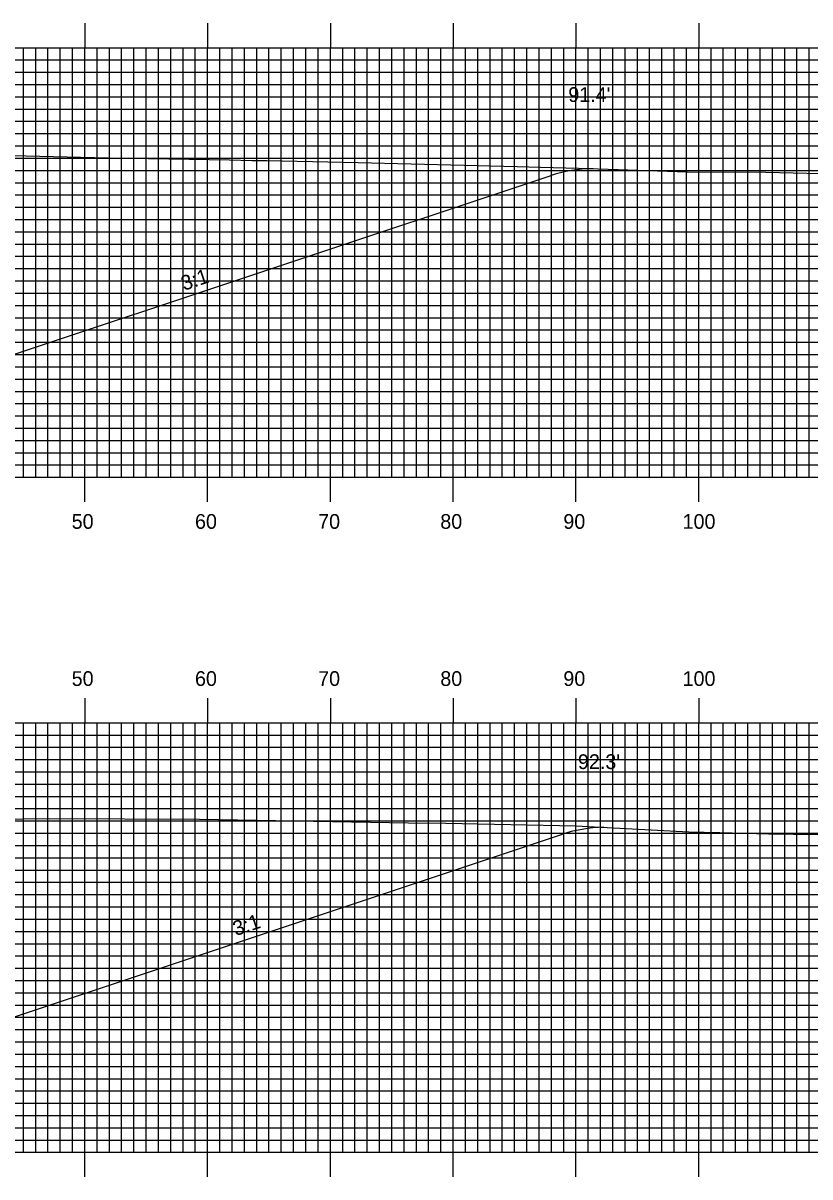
# Model space of a CAD drawing. Extents: x 1796420 to 1796763, y 442591 to 442811.
# Drawn here: x 1796630.9 to 1796695, y 442666.7 to 442760.7 of the extents above; entities that cross this region are included whole.
import ezdxf

# ---------------------------------------------------------------- set-up
doc = ezdxf.new("R2010")
doc.units = 0
for name, color, linetype in [('ANNOTATION', 7, 'Continuous'), ('D_Roadway_SlopeLines', 7, 'Continuous'), ('D_Text_Standard', 7, 'Continuous'), ('H_V ANNOTATION', 7, 'Continuous'), ('MAJOR', 7, 'Continuous'), ('MINOR', 7, 'Continuous'), ('S_Roadway_Centerline', 7, 'Continuous')]:
    doc.layers.add(name, color=color, linetype=linetype)

msp = doc.modelspace()

# ---------------------------------------------------------------- linework, layer by layer
at = {"layer": 'D_Roadway_SlopeLines'}
msp.add_line((1796620.079, 442730.323), (1796673.792, 442748.228), dxfattribs=at)
msp.add_lwpolyline([(1796621.053, 442678.665), (1796627.053, 442678.665), (1796674.718, 442694.554)], dxfattribs=at)
for centre, radius, start, end in [((1796677.352, 442737.548), 11.257, 90.17452, 108.43495), ((1796678.416, 442683.46), 11.694, 91.12543, 108.71551)]:
    msp.add_arc(centre, radius, start, end, dxfattribs=at)
at = {"layer": 'MAJOR'}
for p, q in [((1796635.905, 442760.669), (1796635.905, 442758.665)), ((1796645.905, 442760.669), (1796645.905, 442758.665)), ((1796655.905, 442760.669), (1796655.905, 442758.665)), ((1796665.905, 442760.669), (1796665.905, 442758.665)), ((1796675.905, 442760.669), (1796675.905, 442758.665)), ((1796685.905, 442760.669), (1796685.905, 442758.665)), ((1796445.905, 442758.665), (1796725.905, 442758.665)), ((1796445.905, 442758.665), (1796725.905, 442758.665)), ((1796635.905, 442723.665), (1796635.905, 442758.665)), ((1796645.905, 442723.665), (1796645.905, 442758.665)), ((1796655.905, 442723.665), (1796655.905, 442758.665)), ((1796665.905, 442723.665), (1796665.905, 442758.665)), ((1796675.905, 442723.665), (1796675.905, 442758.665)), ((1796685.905, 442723.665), (1796685.905, 442758.665)), ((1796445.905, 442753.665), (1796725.905, 442753.665)), ((1796445.905, 442748.665), (1796725.905, 442748.665)), ((1796445.905, 442743.665), (1796725.905, 442743.665)), ((1796445.905, 442738.665), (1796725.905, 442738.665)), ((1796445.905, 442733.665), (1796725.905, 442733.665)), ((1796445.905, 442728.665), (1796725.905, 442728.665)), ((1796445.905, 442723.665), (1796725.905, 442723.665)), ((1796445.905, 442723.665), (1796725.905, 442723.665)), ((1796635.905, 442721.661), (1796635.905, 442723.665)), ((1796645.905, 442721.661), (1796645.905, 442723.665)), ((1796655.905, 442721.661), (1796655.905, 442723.665)), ((1796665.905, 442721.661), (1796665.905, 442723.665)), ((1796675.905, 442721.661), (1796675.905, 442723.665)), ((1796685.905, 442721.661), (1796685.905, 442723.665)), ((1796635.905, 442705.669), (1796635.905, 442703.665)), ((1796645.905, 442705.669), (1796645.905, 442703.665)), ((1796655.905, 442705.669), (1796655.905, 442703.665)), ((1796665.905, 442705.669), (1796665.905, 442703.665)), ((1796675.905, 442705.669), (1796675.905, 442703.665)), ((1796685.905, 442705.669), (1796685.905, 442703.665)), ((1796445.905, 442703.665), (1796725.905, 442703.665)), ((1796445.905, 442703.665), (1796725.905, 442703.665)), ((1796635.905, 442668.665), (1796635.905, 442703.665)), ((1796645.905, 442668.665), (1796645.905, 442703.665)), ((1796655.905, 442668.665), (1796655.905, 442703.665)), ((1796665.905, 442668.665), (1796665.905, 442703.665)), ((1796675.905, 442668.665), (1796675.905, 442703.665)), ((1796685.905, 442668.665), (1796685.905, 442703.665)), ((1796445.905, 442698.665), (1796725.905, 442698.665)), ((1796445.905, 442693.665), (1796725.905, 442693.665)), ((1796445.905, 442688.665), (1796725.905, 442688.665)), ((1796445.905, 442683.665), (1796725.905, 442683.665)), ((1796445.905, 442678.665), (1796725.905, 442678.665)), ((1796445.905, 442673.665), (1796725.905, 442673.665)), ((1796445.905, 442668.665), (1796725.905, 442668.665)), ((1796445.905, 442668.665), (1796725.905, 442668.665)), ((1796635.905, 442666.661), (1796635.905, 442668.665)), ((1796645.905, 442666.661), (1796645.905, 442668.665)), ((1796655.905, 442666.661), (1796655.905, 442668.665)), ((1796665.905, 442666.661), (1796665.905, 442668.665)), ((1796675.905, 442666.661), (1796675.905, 442668.665)), ((1796685.905, 442666.661), (1796685.905, 442668.665))]:
    msp.add_line(p, q, dxfattribs=at)
at = {"layer": 'MINOR'}
for p, q in [((1796630.905, 442723.665), (1796630.905, 442758.665)), ((1796631.905, 442723.665), (1796631.905, 442758.665)), ((1796632.905, 442723.665), (1796632.905, 442758.665)), ((1796633.905, 442723.665), (1796633.905, 442758.665)), ((1796634.905, 442723.665), (1796634.905, 442758.665)), ((1796636.905, 442723.665), (1796636.905, 442758.665)), ((1796637.905, 442723.665), (1796637.905, 442758.665)), ((1796638.905, 442723.665), (1796638.905, 442758.665)), ((1796639.905, 442723.665), (1796639.905, 442758.665)), ((1796640.905, 442723.665), (1796640.905, 442758.665)), ((1796641.905, 442723.665), (1796641.905, 442758.665)), ((1796642.905, 442723.665), (1796642.905, 442758.665)), ((1796643.905, 442723.665), (1796643.905, 442758.665)), ((1796644.905, 442723.665), (1796644.905, 442758.665)), ((1796646.905, 442723.665), (1796646.905, 442758.665)), ((1796647.905, 442723.665), (1796647.905, 442758.665)), ((1796648.905, 442723.665), (1796648.905, 442758.665)), ((1796649.905, 442723.665), (1796649.905, 442758.665)), ((1796650.905, 442723.665), (1796650.905, 442758.665)), ((1796651.905, 442723.665), (1796651.905, 442758.665)), ((1796652.905, 442723.665), (1796652.905, 442758.665)), ((1796653.905, 442723.665), (1796653.905, 442758.665)), ((1796654.905, 442723.665), (1796654.905, 442758.665)), ((1796656.905, 442723.665), (1796656.905, 442758.665)), ((1796657.905, 442723.665), (1796657.905, 442758.665)), ((1796658.905, 442723.665), (1796658.905, 442758.665)), ((1796659.905, 442723.665), (1796659.905, 442758.665)), ((1796660.905, 442723.665), (1796660.905, 442758.665)), ((1796661.905, 442723.665), (1796661.905, 442758.665)), ((1796662.905, 442723.665), (1796662.905, 442758.665)), ((1796663.905, 442723.665), (1796663.905, 442758.665)), ((1796664.905, 442723.665), (1796664.905, 442758.665)), ((1796666.905, 442723.665), (1796666.905, 442758.665)), ((1796667.905, 442723.665), (1796667.905, 442758.665)), ((1796668.905, 442723.665), (1796668.905, 442758.665)), ((1796669.905, 442723.665), (1796669.905, 442758.665)), ((1796670.905, 442723.665), (1796670.905, 442758.665)), ((1796671.905, 442723.665), (1796671.905, 442758.665)), ((1796672.905, 442723.665), (1796672.905, 442758.665)), ((1796673.905, 442723.665), (1796673.905, 442758.665)), ((1796674.905, 442723.665), (1796674.905, 442758.665)), ((1796676.905, 442723.665), (1796676.905, 442758.665)), ((1796677.905, 442723.665), (1796677.905, 442758.665)), ((1796678.905, 442723.665), (1796678.905, 442758.665)), ((1796679.905, 442723.665), (1796679.905, 442758.665)), ((1796680.905, 442723.665), (1796680.905, 442758.665)), ((1796681.905, 442723.665), (1796681.905, 442758.665)), ((1796682.905, 442723.665), (1796682.905, 442758.665)), ((1796683.905, 442723.665), (1796683.905, 442758.665)), ((1796684.905, 442723.665), (1796684.905, 442758.665)), ((1796686.905, 442723.665), (1796686.905, 442758.665)), ((1796687.905, 442723.665), (1796687.905, 442758.665)), ((1796688.905, 442723.665), (1796688.905, 442758.665)), ((1796689.905, 442723.665), (1796689.905, 442758.665)), ((1796690.905, 442723.665), (1796690.905, 442758.665)), ((1796691.905, 442723.665), (1796691.905, 442758.665)), ((1796692.905, 442723.665), (1796692.905, 442758.665)), ((1796693.905, 442723.665), (1796693.905, 442758.665)), ((1796694.905, 442723.665), (1796694.905, 442758.665)), ((1796445.905, 442757.665), (1796725.905, 442757.665)), ((1796445.905, 442756.665), (1796725.905, 442756.665)), ((1796445.905, 442755.665), (1796725.905, 442755.665)), ((1796445.905, 442754.665), (1796725.905, 442754.665)), ((1796445.905, 442752.665), (1796725.905, 442752.665)), ((1796445.905, 442751.665), (1796725.905, 442751.665)), ((1796445.905, 442750.665), (1796725.905, 442750.665)), ((1796445.905, 442749.665), (1796725.905, 442749.665)), ((1796445.905, 442747.665), (1796725.905, 442747.665)), ((1796445.905, 442746.665), (1796725.905, 442746.665)), ((1796445.905, 442745.665), (1796725.905, 442745.665)), ((1796445.905, 442744.665), (1796725.905, 442744.665)), ((1796445.905, 442742.665), (1796725.905, 442742.665)), ((1796445.905, 442741.665), (1796725.905, 442741.665)), ((1796445.905, 442740.665), (1796725.905, 442740.665)), ((1796445.905, 442739.665), (1796725.905, 442739.665)), ((1796445.905, 442737.665), (1796725.905, 442737.665)), ((1796445.905, 442736.665), (1796725.905, 442736.665)), ((1796445.905, 442735.665), (1796725.905, 442735.665)), ((1796445.905, 442734.665), (1796725.905, 442734.665)), ((1796445.905, 442732.665), (1796725.905, 442732.665)), ((1796445.905, 442731.665), (1796725.905, 442731.665)), ((1796445.905, 442730.665), (1796725.905, 442730.665)), ((1796445.905, 442729.665), (1796725.905, 442729.665)), ((1796445.905, 442727.665), (1796725.905, 442727.665)), ((1796445.905, 442726.665), (1796725.905, 442726.665)), ((1796445.905, 442725.665), (1796725.905, 442725.665)), ((1796445.905, 442724.665), (1796725.905, 442724.665)), ((1796630.905, 442668.665), (1796630.905, 442703.665)), ((1796631.905, 442668.665), (1796631.905, 442703.665)), ((1796632.905, 442668.665), (1796632.905, 442703.665)), ((1796633.905, 442668.665), (1796633.905, 442703.665)), ((1796634.905, 442668.665), (1796634.905, 442703.665)), ((1796636.905, 442668.665), (1796636.905, 442703.665)), ((1796637.905, 442668.665), (1796637.905, 442703.665)), ((1796638.905, 442668.665), (1796638.905, 442703.665)), ((1796639.905, 442668.665), (1796639.905, 442703.665)), ((1796640.905, 442668.665), (1796640.905, 442703.665)), ((1796641.905, 442668.665), (1796641.905, 442703.665)), ((1796642.905, 442668.665), (1796642.905, 442703.665)), ((1796643.905, 442668.665), (1796643.905, 442703.665)), ((1796644.905, 442668.665), (1796644.905, 442703.665)), ((1796646.905, 442668.665), (1796646.905, 442703.665)), ((1796647.905, 442668.665), (1796647.905, 442703.665)), ((1796648.905, 442668.665), (1796648.905, 442703.665)), ((1796649.905, 442668.665), (1796649.905, 442703.665)), ((1796650.905, 442668.665), (1796650.905, 442703.665)), ((1796651.905, 442668.665), (1796651.905, 442703.665)), ((1796652.905, 442668.665), (1796652.905, 442703.665)), ((1796653.905, 442668.665), (1796653.905, 442703.665)), ((1796654.905, 442668.665), (1796654.905, 442703.665)), ((1796656.905, 442668.665), (1796656.905, 442703.665)), ((1796657.905, 442668.665), (1796657.905, 442703.665)), ((1796658.905, 442668.665), (1796658.905, 442703.665)), ((1796659.905, 442668.665), (1796659.905, 442703.665)), ((1796660.905, 442668.665), (1796660.905, 442703.665)), ((1796661.905, 442668.665), (1796661.905, 442703.665)), ((1796662.905, 442668.665), (1796662.905, 442703.665)), ((1796663.905, 442668.665), (1796663.905, 442703.665)), ((1796664.905, 442668.665), (1796664.905, 442703.665)), ((1796666.905, 442668.665), (1796666.905, 442703.665)), ((1796667.905, 442668.665), (1796667.905, 442703.665)), ((1796668.905, 442668.665), (1796668.905, 442703.665)), ((1796669.905, 442668.665), (1796669.905, 442703.665)), ((1796670.905, 442668.665), (1796670.905, 442703.665)), ((1796671.905, 442668.665), (1796671.905, 442703.665)), ((1796672.905, 442668.665), (1796672.905, 442703.665)), ((1796673.905, 442668.665), (1796673.905, 442703.665)), ((1796674.905, 442668.665), (1796674.905, 442703.665)), ((1796676.905, 442668.665), (1796676.905, 442703.665)), ((1796677.905, 442668.665), (1796677.905, 442703.665)), ((1796678.905, 442668.665), (1796678.905, 442703.665)), ((1796679.905, 442668.665), (1796679.905, 442703.665)), ((1796680.905, 442668.665), (1796680.905, 442703.665)), ((1796681.905, 442668.665), (1796681.905, 442703.665)), ((1796682.905, 442668.665), (1796682.905, 442703.665)), ((1796683.905, 442668.665), (1796683.905, 442703.665)), ((1796684.905, 442668.665), (1796684.905, 442703.665)), ((1796686.905, 442668.665), (1796686.905, 442703.665)), ((1796687.905, 442668.665), (1796687.905, 442703.665)), ((1796688.905, 442668.665), (1796688.905, 442703.665)), ((1796689.905, 442668.665), (1796689.905, 442703.665)), ((1796690.905, 442668.665), (1796690.905, 442703.665)), ((1796691.905, 442668.665), (1796691.905, 442703.665)), ((1796692.905, 442668.665), (1796692.905, 442703.665)), ((1796693.905, 442668.665), (1796693.905, 442703.665)), ((1796694.905, 442668.665), (1796694.905, 442703.665)), ((1796445.905, 442702.665), (1796725.905, 442702.665)), ((1796445.905, 442701.665), (1796725.905, 442701.665)), ((1796445.905, 442700.665), (1796725.905, 442700.665)), ((1796445.905, 442699.665), (1796725.905, 442699.665)), ((1796445.905, 442697.665), (1796725.905, 442697.665)), ((1796445.905, 442696.665), (1796725.905, 442696.665)), ((1796445.905, 442695.665), (1796725.905, 442695.665)), ((1796445.905, 442694.665), (1796725.905, 442694.665)), ((1796445.905, 442692.665), (1796725.905, 442692.665)), ((1796445.905, 442691.665), (1796725.905, 442691.665)), ((1796445.905, 442690.665), (1796725.905, 442690.665)), ((1796445.905, 442689.665), (1796725.905, 442689.665)), ((1796445.905, 442687.665), (1796725.905, 442687.665)), ((1796445.905, 442686.665), (1796725.905, 442686.665)), ((1796445.905, 442685.665), (1796725.905, 442685.665)), ((1796445.905, 442684.665), (1796725.905, 442684.665)), ((1796445.905, 442682.665), (1796725.905, 442682.665)), ((1796445.905, 442681.665), (1796725.905, 442681.665)), ((1796445.905, 442680.665), (1796725.905, 442680.665)), ((1796445.905, 442679.665), (1796725.905, 442679.665)), ((1796445.905, 442677.665), (1796725.905, 442677.665)), ((1796445.905, 442676.665), (1796725.905, 442676.665)), ((1796445.905, 442675.665), (1796725.905, 442675.665)), ((1796445.905, 442674.665), (1796725.905, 442674.665)), ((1796445.905, 442672.665), (1796725.905, 442672.665)), ((1796445.905, 442671.665), (1796725.905, 442671.665)), ((1796445.905, 442670.665), (1796725.905, 442670.665)), ((1796445.905, 442669.665), (1796725.905, 442669.665))]:
    msp.add_line(p, q, dxfattribs=at)
at = {"layer": 'S_Roadway_Centerline'}
for points in [[(1796626.071, 442749.969), (1796631.131, 442749.849), (1796637.82, 442749.683), (1796647.695, 442749.521), (1796649.505, 442749.486), (1796650.731, 442749.461), (1796658.17, 442749.303), (1796671.118, 442748.982), (1796673.023, 442748.918), (1796676.121, 442748.846), (1796684.971, 442748.547), (1796691.365, 442748.521), (1796704.774, 442748.192), (1796708.367, 442748.062), (1796710.756, 442747.974), (1796720.517, 442747.622), (1796725.905, 442747.531)], [(1796628.631, 442695.819), (1796633.062, 442695.871), (1796645.252, 442695.8), (1796662.272, 442695.504), (1796665.317, 442695.495), (1796675.895, 442695.275), (1796685.095, 442694.781), (1796687.609, 442694.728), (1796691.607, 442694.613), (1796699.665, 442694.494), (1796704.871, 442694.35), (1796720.251, 442694.317), (1796722.817, 442694.352), (1796724.551, 442694.313), (1796725.905, 442694.283)]]:
    msp.add_lwpolyline(points, dxfattribs=at)

# ---------------------------------------------------------------- texts
at = {"layer": 'ANNOTATION'}
for p in [(1796643.983, 442738.854), (1796643.983, 442738.854), (1796648.2, 442686.277), (1796648.2, 442686.277)]:
    msp.add_text('3:1', height=1.2, rotation=18.43495, dxfattribs=at).set_placement(p)
at = {"layer": 'D_Text_Standard'}
for s, p in [("91.4'", (1796675.279, 442754.247)), ("92.3'", (1796676.066, 442699.892))]:
    msp.add_text(s, height=1.2, dxfattribs=at).set_placement(p)
at = {"layer": 'H_V ANNOTATION'}
for s, p in [('50', (1796634.835, 442719.465)), ('60', (1796644.878, 442719.465)), ('70', (1796654.909, 442719.465)), ('80', (1796664.856, 442719.465)), ('90', (1796674.878, 442719.465)), ('100', (1796684.589, 442719.465)), ('50', (1796634.835, 442706.665)), ('60', (1796644.878, 442706.665)), ('70', (1796654.909, 442706.665)), ('80', (1796664.856, 442706.665)), ('90', (1796674.878, 442706.665)), ('100', (1796684.589, 442706.665))]:
    msp.add_text(s, height=1.2, dxfattribs=at).set_placement(p)

doc.saveas('drawing.dxf')
